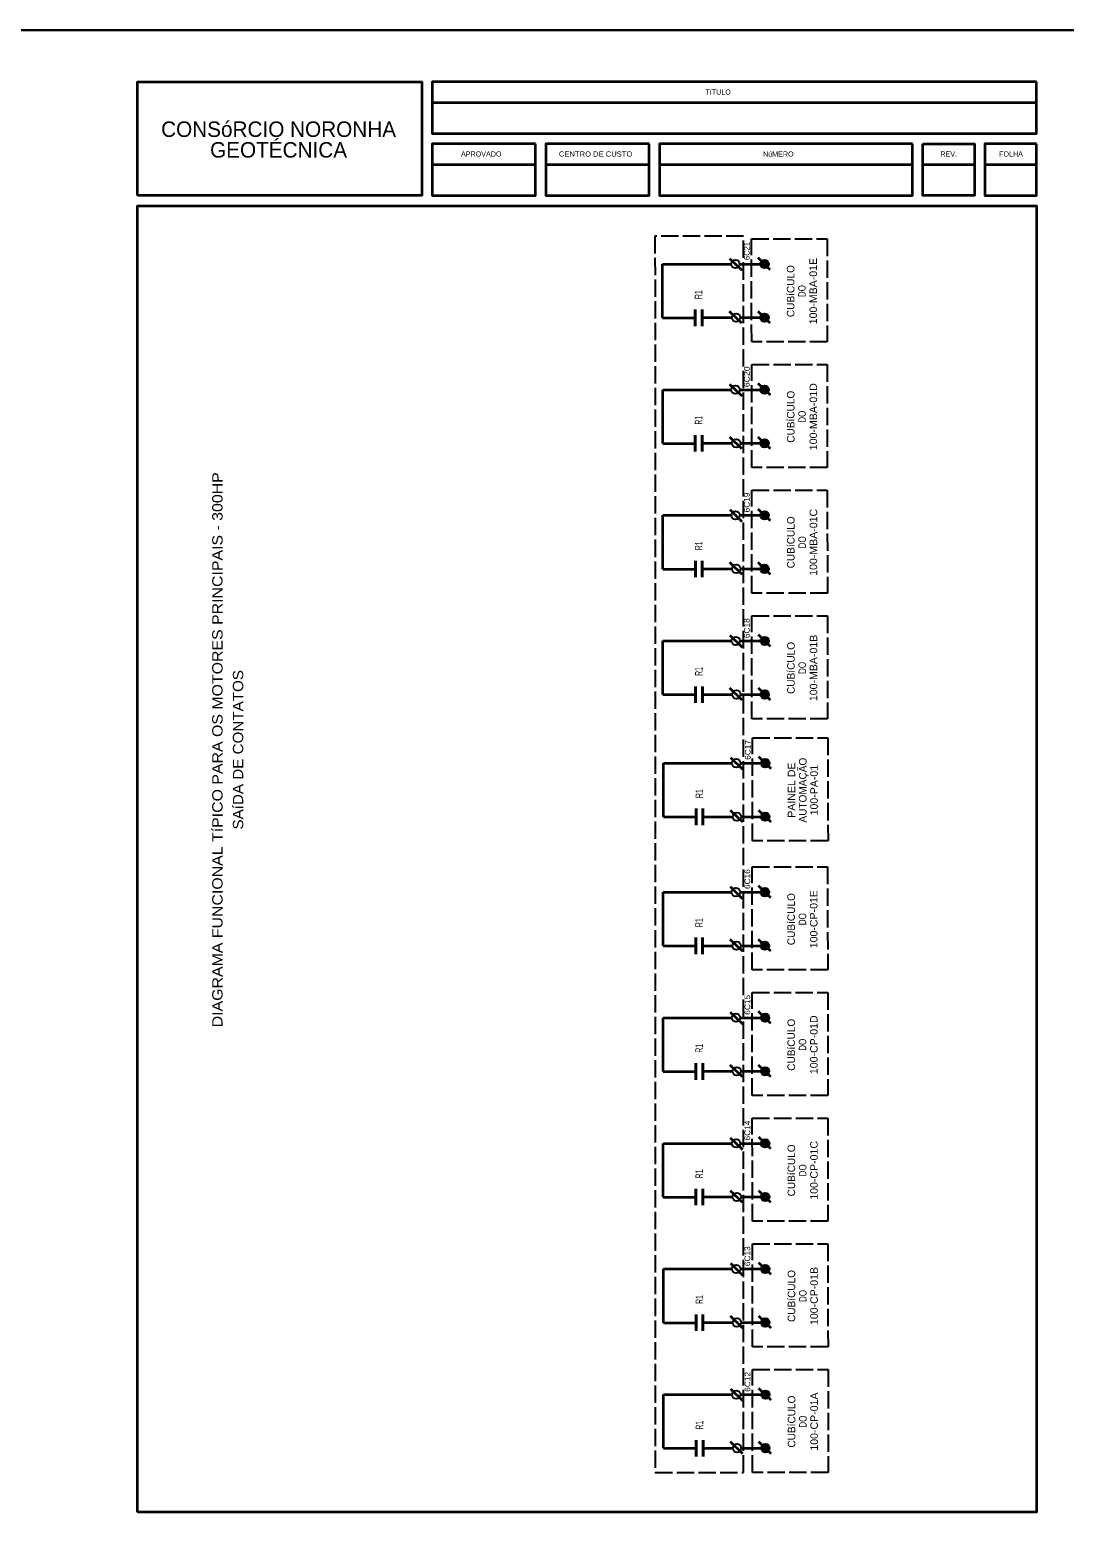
# Model space of a CAD drawing. Extents: x -4160 to -2690, y -474 to 714.
# Drawn here: x -3315.6 to -3115.3, y -171.5 to 120.5 of the extents above; entities that cross this region are included whole.
import ezdxf
from ezdxf.enums import TextEntityAlignment as Align

# ---------------------------------------------------------------- set-up
doc = ezdxf.new("R2010")
doc.units = 0
doc.header["$LTSCALE"] = 0.56
doc.linetypes.add('LONG_DASHED', pattern=[7.5, 6, -1.5])
doc.layers.add('2', color=7, linetype='Continuous', lineweight=25)
doc.layers.add('5', color=7, linetype='Continuous', lineweight=35)

msp = doc.modelspace()

# ---------------------------------------------------------------- hatches: boundary and pattern name
at = {"layer": '2'}
for points in [[(-3173.4161, 74.3556, 1), (-3173.4161, 75.9942, 1)], [(-3173.4161, 63.9813, 1), (-3173.4161, 65.6199, 1)], [(-3173.396, 50.0284, 1), (-3173.396, 51.6669, 1)], [(-3173.396, 39.6541, 1), (-3173.396, 41.2927, 1)], [(-3173.3758, 25.7011, 1), (-3173.3758, 27.3397, 1)], [(-3173.3758, 15.3269, 1), (-3173.3758, 16.9654, 1)], [(-3173.3557, 1.3739, 1), (-3173.3557, 3.0125, 1)], [(-3173.3557, -9.0004, 1), (-3173.3557, -7.3618, 1)], [(-3173.2551, -22.2941, 1), (-3173.2551, -20.6556, 1)], [(-3173.2551, -32.6684, 1), (-3173.2551, -31.0298, 1)], [(-3173.3155, -47.2806, 1), (-3173.3155, -45.642, 1)], [(-3173.3155, -57.6549, 1), (-3173.3155, -56.0163, 1)], [(-3173.2954, -71.6078, 1), (-3173.2954, -69.9693, 1)], [(-3173.2954, -81.9821, 1), (-3173.2954, -80.3435, 1)], [(-3173.2752, -95.9351, 1), (-3173.2752, -94.2965, 1)], [(-3173.2752, -106.3093, 1), (-3173.2752, -104.6708, 1)], [(-3173.2551, -120.2623, 1), (-3173.2551, -118.6238, 1)], [(-3173.2551, -130.6366, 1), (-3173.2551, -128.998, 1)], [(-3173.235, -144.5896, 1), (-3173.235, -142.951, 1)], [(-3173.235, -154.9638, 1), (-3173.235, -153.3252, 1)]]:
    msp.add_hatch(color=256, dxfattribs=at).paths.add_polyline_path(points)

# ---------------------------------------------------------------- linework, layer by layer
at = {"layer": '2', "lineweight": 35}
for p, q in [((-3177.7388, 73.9069), (-3180.1052, 76.2013)), ((-3174.7218, 76.4428), (-3172.3554, 74.1485)), ((-3193.137, 75.1749), (-3179.8638, 75.1749)), ((-3193.137, 64.7686), (-3193.137, 75.1749)), ((-3178.2251, 75.1749), (-3174.2354, 75.1749)), ((-3193.137, 64.7686), (-3186.816, 64.7686)), ((-3185.4921, 64.8007), (-3179.7269, 64.8007)), ((-3180.2134, 66.0709), (-3177.8469, 63.7767)), ((-3178.0883, 64.8007), (-3174.2354, 64.8007)), ((-3174.7218, 66.0686), (-3172.3554, 63.7743)), ((-3193.1168, 50.8476), (-3179.8436, 50.8476)), ((-3193.1168, 40.4414), (-3193.1168, 50.8476)), ((-3177.7187, 49.5797), (-3180.085, 51.874)), ((-3178.205, 50.8476), (-3174.2153, 50.8476)), ((-3174.7017, 52.1156), (-3172.3353, 49.8214)), ((-3180.1932, 41.7437), (-3177.8268, 39.4493)), ((-3174.7017, 41.7413), (-3172.3353, 39.447)), ((-3193.1168, 40.4414), (-3186.7959, 40.4414)), ((-3185.4721, 40.4734), (-3179.7068, 40.4734)), ((-3178.0682, 40.4734), (-3174.2153, 40.4734)), ((-3193.0967, 26.5204), (-3179.8236, 26.5204)), ((-3193.0967, 16.114), (-3193.0967, 26.5204)), ((-3177.6985, 25.2524), (-3180.065, 27.5468)), ((-3178.185, 26.5204), (-3174.1952, 26.5204)), ((-3174.6815, 27.7884), (-3172.3152, 25.494)), ((-3193.0967, 16.114), (-3186.7757, 16.114)), ((-3185.4518, 16.1462), (-3179.6868, 16.1462)), ((-3180.173, 17.4165), (-3177.8067, 15.1221)), ((-3178.0481, 16.1462), (-3174.1952, 16.1462)), ((-3174.6815, 17.4141), (-3172.3152, 15.1198)), ((-3177.6783, 0.9252), (-3180.0448, 3.2195)), ((-3174.6614, 3.4611), (-3172.295, 1.1668)), ((-3193.0766, 2.1932), (-3179.8034, 2.1932)), ((-3193.0766, -8.2132), (-3193.0766, 2.1932)), ((-3178.1648, 2.1932), (-3174.175, 2.1932)), ((-3193.0766, -8.2132), (-3186.7556, -8.2132)), ((-3185.4318, -8.1811), (-3179.6666, -8.1811)), ((-3180.153, -6.9109), (-3177.7866, -9.205)), ((-3178.028, -8.1811), (-3174.175, -8.1811)), ((-3174.6614, -6.9131), (-3172.295, -9.2074)), ((-3174.5608, -20.2069), (-3172.1945, -22.5012)), ((-3192.976, -21.4748), (-3179.7028, -21.4748)), ((-3192.976, -31.8812), (-3192.976, -21.4748)), ((-3177.5778, -22.7428), (-3179.9442, -20.4485)), ((-3178.0642, -21.4748), (-3174.0745, -21.4748)), ((-3192.976, -31.8812), (-3186.655, -31.8812)), ((-3185.3311, -31.8491), (-3179.566, -31.8491)), ((-3180.0524, -30.5788), (-3177.686, -32.8732)), ((-3177.9274, -31.8491), (-3174.0745, -31.8491)), ((-3174.5608, -30.5811), (-3172.1945, -32.8755)), ((-3193.0364, -46.4613), (-3179.7632, -46.4613)), ((-3193.0364, -56.8677), (-3193.0364, -46.4613)), ((-3177.6382, -47.7293), (-3180.0046, -45.4349)), ((-3178.1245, -46.4613), (-3174.1348, -46.4613)), ((-3174.6212, -45.1933), (-3172.2548, -47.4877)), ((-3193.0364, -56.8677), (-3186.7153, -56.8677)), ((-3185.3915, -56.8356), (-3179.6263, -56.8356)), ((-3180.1128, -55.5653), (-3177.7463, -57.8596)), ((-3177.9877, -56.8356), (-3174.1348, -56.8356)), ((-3174.6212, -55.5676), (-3172.2548, -57.8619)), ((-3177.618, -72.0565), (-3179.9844, -69.7622)), ((-3174.6011, -69.5206), (-3172.2347, -71.8149)), ((-3193.0163, -70.7885), (-3179.743, -70.7885)), ((-3193.0163, -81.1949), (-3193.0163, -70.7885)), ((-3178.1044, -70.7885), (-3174.1147, -70.7885)), ((-3193.0163, -81.1949), (-3186.6953, -81.1949)), ((-3185.3714, -81.1628), (-3179.6062, -81.1628)), ((-3180.0927, -79.8925), (-3177.7262, -82.1869)), ((-3177.9676, -81.1628), (-3174.1147, -81.1628)), ((-3174.6011, -79.8948), (-3172.2347, -82.1892)), ((-3192.9961, -95.1158), (-3179.723, -95.1158)), ((-3192.9961, -105.5221), (-3192.9961, -95.1158)), ((-3177.598, -96.3837), (-3179.9643, -94.0895)), ((-3178.0843, -95.1158), (-3174.0945, -95.1158)), ((-3174.5809, -93.8478), (-3172.2145, -96.1422)), ((-3180.0725, -104.2198), (-3177.7061, -106.5141)), ((-3174.5809, -104.2221), (-3172.2145, -106.5164)), ((-3192.9961, -105.5221), (-3186.6751, -105.5221)), ((-3185.3513, -105.49), (-3179.5862, -105.49)), ((-3177.9474, -105.49), (-3174.0945, -105.49)), ((-3192.976, -119.443), (-3179.7028, -119.443)), ((-3192.976, -129.8494), (-3192.976, -119.443)), ((-3177.5778, -120.711), (-3179.9442, -118.4166)), ((-3178.0642, -119.443), (-3174.0745, -119.443)), ((-3174.5608, -118.1752), (-3172.1945, -120.4694)), ((-3192.976, -129.8494), (-3186.655, -129.8494)), ((-3185.3311, -129.8173), (-3179.566, -129.8173)), ((-3180.0524, -128.547), (-3177.686, -130.8413)), ((-3177.9274, -129.8173), (-3174.0745, -129.8173)), ((-3174.5608, -128.5494), (-3172.1945, -130.8437)), ((-3177.5576, -145.0382), (-3179.9241, -142.744)), ((-3174.5407, -142.5023), (-3172.1743, -144.7966)), ((-3192.9559, -143.7703), (-3179.6827, -143.7703)), ((-3192.9559, -154.1766), (-3192.9559, -143.7703)), ((-3178.0441, -143.7703), (-3174.0543, -143.7703)), ((-3192.9559, -154.1766), (-3186.6349, -154.1766)), ((-3185.311, -154.1446), (-3179.5459, -154.1446)), ((-3180.0323, -152.8742), (-3177.6659, -155.1686)), ((-3177.9072, -154.1446), (-3174.0543, -154.1446)), ((-3174.5407, -152.8765), (-3172.1743, -155.1709))]:
    msp.add_line(p, q, dxfattribs=at)
at = {"layer": '2'}
for p, q in [((-3180.564, 75.1749), (-3179.8638, 75.1749)), ((-3180.5439, 50.8476), (-3179.8436, 50.8476)), ((-3180.5237, 26.5204), (-3179.8236, 26.5204)), ((-3180.5036, 2.1932), (-3179.8034, 2.1932)), ((-3180.4031, -21.4748), (-3179.7028, -21.4748)), ((-3180.4634, -46.4613), (-3179.7632, -46.4613)), ((-3180.4433, -70.7885), (-3179.743, -70.7885)), ((-3180.4232, -95.1158), (-3179.723, -95.1158)), ((-3180.4031, -119.443), (-3179.7028, -119.443)), ((-3180.3828, -143.7703), (-3179.6827, -143.7703))]:
    msp.add_line(p, q, dxfattribs=at)
at = {"layer": '2', "lineweight": 40}
for p, q in [((-3186.816, 63.1745), (-3186.816, 66.3626)), ((-3185.4921, 63.1745), (-3185.4921, 66.3626)), ((-3186.7959, 38.8473), (-3186.7959, 42.0354)), ((-3185.4721, 38.8473), (-3185.4721, 42.0354)), ((-3186.7757, 14.52), (-3186.7757, 17.7081)), ((-3185.4518, 14.52), (-3185.4518, 17.7081)), ((-3186.7556, -9.8071), (-3186.7556, -6.6192)), ((-3185.4318, -9.8071), (-3185.4318, -6.6192)), ((-3186.655, -33.4752), (-3186.655, -30.2871)), ((-3185.3311, -33.4752), (-3185.3311, -30.2871)), ((-3186.7153, -58.4617), (-3186.7153, -55.2736)), ((-3185.3915, -58.4617), (-3185.3915, -55.2736)), ((-3186.6953, -82.7889), (-3186.6953, -79.6009)), ((-3185.3714, -82.7889), (-3185.3714, -79.6009)), ((-3186.6751, -107.1161), (-3186.6751, -103.9281)), ((-3185.3513, -107.1161), (-3185.3513, -103.9281)), ((-3186.655, -131.4434), (-3186.655, -128.2553)), ((-3185.3311, -131.4434), (-3185.3311, -128.2553)), ((-3186.6349, -155.7706), (-3186.6349, -152.5825)), ((-3185.311, -155.7706), (-3185.311, -152.5825))]:
    msp.add_line(p, q, dxfattribs=at)
at = {"layer": '2', "linetype": 'LONG_DASHED'}
for points in [[(-3177.4596, -158.8461), (-3177.4796, 80.6034), (-3194.604, 80.6034), (-3194.5838, -158.8461)], [(-3161.2708, 60.099), (-3175.8873, 60.099), (-3175.9076, 80.0523), (-3161.291, 80.0523)], [(-3161.2506, 35.7718), (-3175.8673, 35.7718), (-3175.8873, 55.725), (-3161.2708, 55.725)], [(-3161.2306, 11.4446), (-3175.8471, 11.4446), (-3175.8673, 31.3978), (-3161.2506, 31.3978)], [(-3161.2104, -12.8827), (-3175.827, -12.8827), (-3175.8471, 7.0706), (-3161.2306, 7.0706)], [(-3161.1098, -36.5506), (-3175.7264, -36.5506), (-3175.7465, -16.5975), (-3161.13, -16.5975)], [(-3161.1702, -61.5372), (-3175.7868, -61.5372), (-3175.807, -41.5839), (-3161.1903, -41.5839)], [(-3161.1501, -85.8644), (-3175.7666, -85.8644), (-3175.7868, -65.9112), (-3161.1702, -65.9112)], [(-3161.13, -110.1917), (-3175.7465, -110.1917), (-3175.7666, -90.2384), (-3161.1501, -90.2384)], [(-3161.1098, -134.5189), (-3175.7264, -134.5189), (-3175.7465, -114.5657), (-3161.13, -114.5657)], [(-3161.0897, -158.8461), (-3175.7064, -158.8461), (-3175.7264, -138.8929), (-3161.1098, -138.8929)]]:
    msp.add_lwpolyline(points, close=True, dxfattribs=at)
at = {"layer": '2'}
for centre in [(-3179.0445, 75.1749), (-3173.4161, 75.1749), (-3178.9076, 64.803), (-3173.4161, 64.8006), (-3179.0244, 50.8476), (-3173.396, 50.8476), (-3178.8875, 40.4757), (-3173.396, 40.4734), (-3179.0042, 26.5204), (-3173.3758, 26.5204), (-3178.8674, 16.1485), (-3173.3758, 16.1461), (-3178.9841, 2.1932), (-3173.3557, 2.1932), (-3178.8473, -8.1788), (-3173.3557, -8.1811), (-3178.8835, -21.4748), (-3173.2551, -21.4748), (-3178.7467, -31.8468), (-3173.2551, -31.8491), (-3178.9439, -46.4613), (-3173.3155, -46.4613), (-3178.807, -56.8332), (-3173.3155, -56.8356), (-3178.9238, -70.7886), (-3173.2954, -70.7886), (-3178.7869, -81.1605), (-3173.2954, -81.1628), (-3178.9036, -95.1158), (-3173.2752, -95.1158), (-3178.7668, -105.4877), (-3173.2752, -105.4901), (-3178.8835, -119.443), (-3173.2551, -119.443), (-3178.7467, -129.815), (-3173.2551, -129.8173), (-3178.8634, -143.7703), (-3173.235, -143.7703), (-3178.7266, -154.1422), (-3173.235, -154.1445)]:
    msp.add_circle(centre, 0.8193, dxfattribs=at)
at = {"layer": '5', "lineweight": 25}
msp.add_line((-3109.7642, 120.48), (-3319.7642, 120.48), dxfattribs=at)
at = {"layer": '5'}
for p, q in [((-3237.7642, 106.48), (-3120.7642, 106.48)), ((-3237.7642, 94.48), (-3217.7642, 94.48)), ((-3215.7642, 94.48), (-3195.7642, 94.48)), ((-3193.7642, 94.48), (-3144.7642, 94.48)), ((-3142.7642, 94.48), (-3132.7642, 94.48)), ((-3130.7642, 94.48), (-3120.7642, 94.48))]:
    msp.add_line(p, q, dxfattribs=at)
at = {"layer": '5', "lineweight": 25}
msp.add_lwpolyline([(-3109.7642, -176.52), (-3319.7642, -176.52), (-3319.7642, 120.48), (-3109.7642, 120.48)], close=True, dxfattribs=at)
at = {"layer": '5'}
for points in [[(-3294.7642, 88.48), (-3294.7642, 110.48), (-3239.7642, 110.48), (-3239.7642, 88.48)], [(-3120.7642, 110.48), (-3237.7642, 110.48), (-3237.7642, 100.48), (-3120.7642, 100.48)], [(-3217.7642, 98.48), (-3237.7642, 98.48), (-3237.7642, 88.48), (-3217.7642, 88.48)], [(-3195.7642, 98.48), (-3215.7642, 98.48), (-3215.7642, 88.48), (-3195.7642, 88.48)], [(-3144.7642, 98.48), (-3193.7642, 98.48), (-3193.7642, 88.48), (-3144.7642, 88.48)], [(-3142.7642, 98.48), (-3132.7642, 98.48), (-3132.7642, 88.48), (-3142.7642, 88.48)], [(-3120.7642, 98.48), (-3130.7642, 98.48), (-3130.7642, 88.48), (-3120.7642, 88.48)], [(-3294.7642, -166.52), (-3294.7642, 86.48), (-3120.7642, 86.48), (-3120.7642, -166.52)]]:
    msp.add_lwpolyline(points, close=True, dxfattribs=at)

# ---------------------------------------------------------------- texts
at = {"layer": '2'}
for s, height, p in [('6C21', 1.093, (-3176.2806, 77.7007)), ('CUBíCULO', 1.458, (-3167.6204, 69.9407)), ('CUBíCULO', 1.458, (-3167.6003, 45.6135)), ('CUBíCULO', 1.458, (-3167.5802, 21.2862)), ('CUBíCULO', 1.458, (-3167.5601, -3.0411)), ('AUTOMAÇÃO', 1.458, (-3165.2725, -26.7091)), ('CUBíCULO', 1.458, (-3167.5199, -51.6956)), ('CUBíCULO', 1.458, (-3167.4998, -76.0228)), ('CUBíCULO', 1.458, (-3167.4795, -100.3501)), ('CUBíCULO', 1.458, (-3167.4595, -124.6774)), ('CUBíCULO', 1.458, (-3167.4394, -149.0045))]:
    msp.add_text(s, height=height, rotation=90, dxfattribs=at).set_placement(p, align=Align.CENTER)
for s, height, width, p in [('100-MBA-01E', 1.458, 1.05, (-3163.2464, 69.9407)), ('DO', 1.458, 0.8, (-3165.4334, 69.9407)), ('R1', 1.458, 0.55, (-3185.4554, 69.2552)), ('6C20', 1.093, 1.15, (-3176.2806, 53.352)), ('100-MBA-01D', 1.458, 1.05, (-3163.2263, 45.6134)), ('R1', 1.458, 0.55, (-3185.4354, 44.928)), ('DO', 1.458, 0.8, (-3165.4133, 45.6134)), ('DIAGRAMA FUNCIONAL TíPICO PARA OS MOTORES PRINCIPAIS - 300HP', 2, 1.15, (-3278.3216, -18.8936)), ('6C19', 1.093, 1.1, (-3176.2806, 29.0034)), ('100-MBA-01C', 1.458, 1.05, (-3163.2062, 21.2862)), ('R1', 1.458, 0.55, (-3185.4153, 20.6008)), ('DO', 1.458, 0.8, (-3165.3932, 21.2862)), ('6C18', 1.093, 1.1, (-3176.2806, 4.6548)), ('100-MBA-01B', 1.458, 1.05, (-3163.1861, -3.0411)), ('DO', 1.458, 0.8, (-3165.3731, -3.0411)), ('SAíDA DE CONTATOS', 2, 1.1, (-3274.3217, -18.8937)), ('R1', 1.458, 0.55, (-3185.395, -3.7265)), ('6C17', 1.093, 1.1, (-3176.0995, -18.9278)), ('PAINEL DE', 1.458, 1.05, (-3167.4595, -26.7092)), ('100-PA-01', 1.458, 1.05, (-3163.0855, -26.7091)), ('R1', 1.458, 0.55, (-3185.2945, -27.3945)), ('6C16', 1.093, 1.1, (-3176.18, -43.9355)), ('100-CP-01E', 1.458, 1.05, (-3163.1459, -51.6956)), ('R1', 1.458, 0.55, (-3185.3548, -52.381)), ('DO', 1.458, 0.8, (-3165.3329, -51.6955)), ('6C15', 1.093, 1.1, (-3176.18, -68.2843)), ('100-CP-01D', 1.458, 1.05, (-3163.1258, -76.0229)), ('DO', 1.458, 0.8, (-3165.3128, -76.0227)), ('R1', 1.458, 0.55, (-3185.3347, -76.7082)), ('6C14', 1.093, 1.1, (-3176.18, -92.6329)), ('100-CP-01C', 1.458, 1.05, (-3163.1055, -100.3501)), ('DO', 1.458, 0.8, (-3165.2925, -100.35)), ('R1', 1.458, 0.55, (-3185.3147, -101.0354)), ('6C13', 1.093, 1.1, (-3176.18, -116.9815)), ('100-CP-01B', 1.458, 1.05, (-3163.0855, -124.6774)), ('R1', 1.458, 0.55, (-3185.2945, -125.3627)), ('DO', 1.458, 0.8, (-3165.2725, -124.6772)), ('6C12', 1.093, 1.1, (-3176.1599, -141.3087)), ('100-CP-01A', 1.458, 1.05, (-3163.0654, -149.0046)), ('DO', 1.458, 0.8, (-3165.2524, -149.0045)), ('R1', 1.458, 0.55, (-3185.2744, -149.69))]:
    msp.add_text(s, height=height, rotation=90, dxfattribs=dict(at, width=width)).set_placement(p, align=Align.CENTER)
at = {"layer": '5'}
for s, height, p in [('TíTULO', 1, (-3182.3847, 107.991)), ('CONSóRCIO NORONHA', 3, (-3267.4749, 99.7961)), ('GEOTÉCNICA', 3, (-3267.475, 95.7961)), ('APROVADO', 1, (-3228.2387, 95.9973)), ('REV.', 1, (-3137.7443, 95.9923)), ('FOLHA', 1, (-3125.6809, 95.9923))]:
    msp.add_text(s, height=height, dxfattribs=at).set_placement(p, align=Align.CENTER)
for s, width, p in [('CENTRO DE CUSTO', 1.1, (-3206.0934, 95.9973)), ('NúMERO', 0.95, (-3170.7228, 95.9923))]:
    msp.add_text(s, height=1, dxfattribs=dict(at, width=width)).set_placement(p, align=Align.CENTER)

doc.saveas('drawing.dxf')
